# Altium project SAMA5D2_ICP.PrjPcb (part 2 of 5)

## Sheet 04 - SAMA5D2 - DDR.SchDoc
size B; CompanyName: Microchip Technology Inc.; Organization: Microchip Technology; Address1: 2355 West Chandler Blvd.; Address2: Chandler, AZ  85224; Address4: USA; DocumentNumber: 5; SheetNumber: 5; SheetTotal: 15; SheetTitle: SAMA5D2 - DDR3L
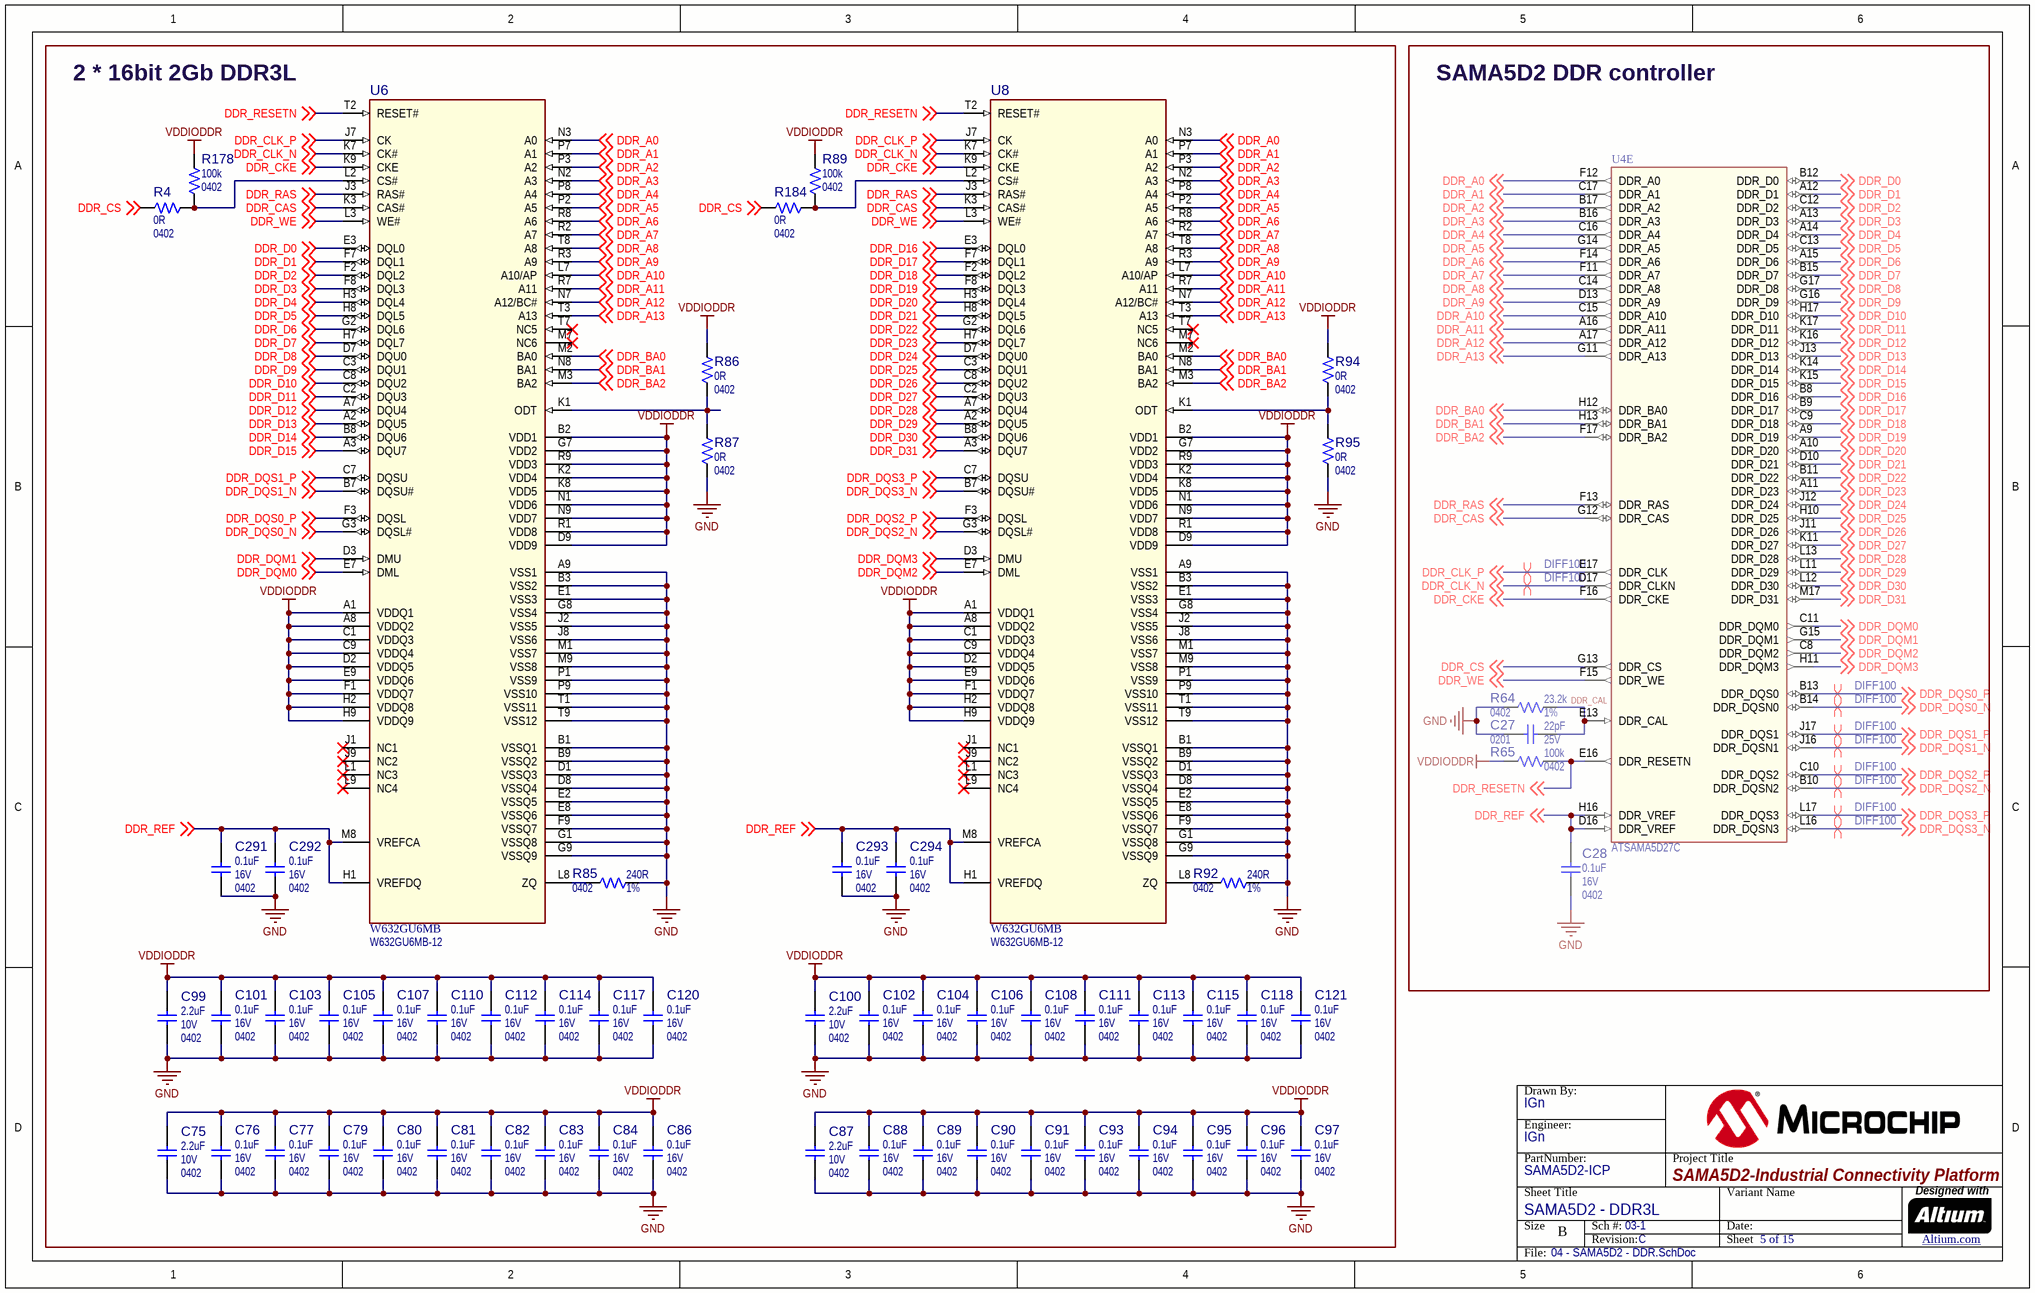
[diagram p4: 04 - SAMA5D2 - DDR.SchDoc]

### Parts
(Parts that share a designator on the sheet are numbered #1, #2 ... from top to bottom, then left to right.)
?#5  (no value)  (graphical)
C27  value 22pF  Voltage: 25V  Package: 0201  [CAP_C_0201]  (hidden comment: Capacitor NP)
C28  value 0.1uF  Voltage: 16V  Package: 0402  [CAP_C_0402]  (hidden comment: Capacitor NP)
C75  value 2.2uF  Voltage: 10V  Package: 0402  [CAP_C_0402]  (hidden comment: Capacitor NP)
C76  value 0.1uF  Voltage: 16V  Package: 0402  [CAP_C_0402]  (hidden comment: Capacitor NP)
C77  value 0.1uF  Voltage: 16V  Package: 0402  [CAP_C_0402]  (hidden comment: Capacitor NP)
C79  value 0.1uF  Voltage: 16V  Package: 0402  [CAP_C_0402]  (hidden comment: Capacitor NP)
C80  value 0.1uF  Voltage: 16V  Package: 0402  [CAP_C_0402]  (hidden comment: Capacitor NP)
C81  value 0.1uF  Voltage: 16V  Package: 0402  [CAP_C_0402]  (hidden comment: Capacitor NP)
C82  value 0.1uF  Voltage: 16V  Package: 0402  [CAP_C_0402]  (hidden comment: Capacitor NP)
C83  value 0.1uF  Voltage: 16V  Package: 0402  [CAP_C_0402]  (hidden comment: Capacitor NP)
C84  value 0.1uF  Voltage: 16V  Package: 0402  [CAP_C_0402]  (hidden comment: Capacitor NP)
C86  value 0.1uF  Voltage: 16V  Package: 0402  [CAP_C_0402]  (hidden comment: Capacitor NP)
C87  value 2.2uF  Voltage: 10V  Package: 0402  [CAP_C_0402]  (hidden comment: Capacitor NP)
C88  value 0.1uF  Voltage: 16V  Package: 0402  [CAP_C_0402]  (hidden comment: Capacitor NP)
C89  value 0.1uF  Voltage: 16V  Package: 0402  [CAP_C_0402]  (hidden comment: Capacitor NP)
C90  value 0.1uF  Voltage: 16V  Package: 0402  [CAP_C_0402]  (hidden comment: Capacitor NP)
C91  value 0.1uF  Voltage: 16V  Package: 0402  [CAP_C_0402]  (hidden comment: Capacitor NP)
C93  value 0.1uF  Voltage: 16V  Package: 0402  [CAP_C_0402]  (hidden comment: Capacitor NP)
C94  value 0.1uF  Voltage: 16V  Package: 0402  [CAP_C_0402]  (hidden comment: Capacitor NP)
C95  value 0.1uF  Voltage: 16V  Package: 0402  [CAP_C_0402]  (hidden comment: Capacitor NP)
C96  value 0.1uF  Voltage: 16V  Package: 0402  [CAP_C_0402]  (hidden comment: Capacitor NP)
C97  value 0.1uF  Voltage: 16V  Package: 0402  [CAP_C_0402]  (hidden comment: Capacitor NP)
C99  value 2.2uF  Voltage: 10V  Package: 0402  [CAP_C_0402]  (hidden comment: Capacitor NP)
C100  value 2.2uF  Voltage: 10V  Package: 0402  [CAP_C_0402]  (hidden comment: Capacitor NP)
C101  value 0.1uF  Voltage: 16V  Package: 0402  [CAP_C_0402]  (hidden comment: Capacitor NP)
C102  value 0.1uF  Voltage: 16V  Package: 0402  [CAP_C_0402]  (hidden comment: Capacitor NP)
C103  value 0.1uF  Voltage: 16V  Package: 0402  [CAP_C_0402]  (hidden comment: Capacitor NP)
C104  value 0.1uF  Voltage: 16V  Package: 0402  [CAP_C_0402]  (hidden comment: Capacitor NP)
C105  value 0.1uF  Voltage: 16V  Package: 0402  [CAP_C_0402]  (hidden comment: Capacitor NP)
C106  value 0.1uF  Voltage: 16V  Package: 0402  [CAP_C_0402]  (hidden comment: Capacitor NP)
C107  value 0.1uF  Voltage: 16V  Package: 0402  [CAP_C_0402]  (hidden comment: Capacitor NP)
C108  value 0.1uF  Voltage: 16V  Package: 0402  [CAP_C_0402]  (hidden comment: Capacitor NP)
C110  value 0.1uF  Voltage: 16V  Package: 0402  [CAP_C_0402]  (hidden comment: Capacitor NP)
C111  value 0.1uF  Voltage: 16V  Package: 0402  [CAP_C_0402]  (hidden comment: Capacitor NP)
C112  value 0.1uF  Voltage: 16V  Package: 0402  [CAP_C_0402]  (hidden comment: Capacitor NP)
C113  value 0.1uF  Voltage: 16V  Package: 0402  [CAP_C_0402]  (hidden comment: Capacitor NP)
C114  value 0.1uF  Voltage: 16V  Package: 0402  [CAP_C_0402]  (hidden comment: Capacitor NP)
C115  value 0.1uF  Voltage: 16V  Package: 0402  [CAP_C_0402]  (hidden comment: Capacitor NP)
C117  value 0.1uF  Voltage: 16V  Package: 0402  [CAP_C_0402]  (hidden comment: Capacitor NP)
C118  value 0.1uF  Voltage: 16V  Package: 0402  [CAP_C_0402]  (hidden comment: Capacitor NP)
C120  value 0.1uF  Voltage: 16V  Package: 0402  [CAP_C_0402]  (hidden comment: Capacitor NP)
C121  value 0.1uF  Voltage: 16V  Package: 0402  [CAP_C_0402]  (hidden comment: Capacitor NP)
C291  value 0.1uF  Voltage: 16V  Package: 0402  [CAP_C_0402]  (hidden comment: Capacitor NP)
C292  value 0.1uF  Voltage: 16V  Package: 0402  [CAP_C_0402]  (hidden comment: Capacitor NP)
C293  value 0.1uF  Voltage: 16V  Package: 0402  [CAP_C_0402]  (hidden comment: Capacitor NP)
C294  value 0.1uF  Voltage: 16V  Package: 0402  [CAP_C_0402]  (hidden comment: Capacitor NP)
R4  value 0R  Package: 0402  [RES_C_0402]  (hidden comment: Resistor)
R64  value 23.2k  Package: 0402  Tolerance: 1%  [RES_C_0402]  (hidden comment: Resistor)
R65  value 100k  Package: 0402  [RES_C_0402]  (hidden comment: Resistor)
R85  value 240R  Package: 0402  Tolerance: 1%  [RES_C_0402]  (hidden comment: Resistor)
R86  value 0R  Package: 0402  [RES_C_0402]  (hidden comment: Resistor)
R87  value 0R  Package: 0402  [RES_C_0402]  (hidden comment: Resistor)
R89  value 100k  Package: 0402  [RES_C_0402]  (hidden comment: Resistor)
R92  value 240R  Package: 0402  Tolerance: 1%  [RES_C_0402]  (hidden comment: Resistor)
R94  value 0R  Package: 0402  [RES_C_0402]  (hidden comment: Resistor)
R95  value 0R  Package: 0402  [RES_C_0402]  (hidden comment: Resistor)
R178  value 100k  Package: 0402  [RES_C_0402]  (hidden comment: Resistor)
R184  value 0R  Package: 0402  [RES_C_0402]  (hidden comment: Resistor)
U4  value ATSAMA5D27C  [LFBGA-289_P0.8_14x14x1.4]  (hidden comment: ATSAMA5D27C LFBGA-289)  (part E of 7)
U6  W632GU6MB  value W632GU6MB-12  [TFBGA-96_13x7.5]
U8  W632GU6MB  value W632GU6MB-12  [TFBGA-96_13x7.5]

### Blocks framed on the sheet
2 * 16bit 2Gb DDR3L: C75-C77 C79-C84 C86-C91 C93-C97 C99-C108 C110-C115 C117 C118 C120 C121 C291-C294 R4 R85-R87 R89 R92 R94 R95 R178 R184 U6 U8
SAMA5D2 DDR controller: C27 C28 R64 R65 U4

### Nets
GND: C27.1 C28.1 C75.1 C76.1 C77.1 C79.1 C80.1 C81.1 C82.1 C83.1 C84.1 C86.1 C87.1 C88.1 C89.1 C90.1 C91.1 C93.1 C94.1 C95.1 C96.1 C97.1 C99.1 C100.1 C101.1 C102.1 C103.1 C104.1 C105.1 C106.1 C107.1 C108.1 C110.1 C111.1 C112.1 C113.1 C114.1 C115.1 C117.1 C118.1 C120.1 C121.1 C291.1 C292.1 C293.1 C294.1 R64.1 R85.1 R87.1 R92.1 R95.1 U6.A9(VSS1) U6.B1(VSSQ1) U6.B3(VSS2) U6.B9(VSSQ2) U6.D1(VSSQ3) U6.D8(VSSQ4) U6.E1(VSS3) U6.E2(VSSQ5) U6.E8(VSSQ6) U6.F9(VSSQ7) U6.G1(VSSQ8) U6.G8(VSS4) U6.G9(VSSQ9) U6.J2(VSS5) U6.J8(VSS6) U6.M1(VSS7) U6.M9(VSS8) U6.P1(VSS9) U6.P9(VSS10) U6.T1(VSS11) U6.T9(VSS12) U8.A9(VSS1) U8.B1(VSSQ1) U8.B3(VSS2) U8.B9(VSSQ2) U8.D1(VSSQ3) U8.D8(VSSQ4) U8.E1(VSS3) U8.E2(VSSQ5) U8.E8(VSSQ6) U8.F9(VSSQ7) U8.G1(VSSQ8) U8.G8(VSS4) U8.G9(VSSQ9) U8.J2(VSS5) U8.J8(VSS6) U8.M1(VSS7) U8.M9(VSS8) U8.P1(VSS9) U8.P9(VSS10) U8.T1(VSS11) U8.T9(VSS12)
VDDIODDR: C75.2 C76.2 C77.2 C79.2 C80.2 C81.2 C82.2 C83.2 C84.2 C86.2 C87.2 C88.2 C89.2 C90.2 C91.2 C93.2 C94.2 C95.2 C96.2 C97.2 C99.2 C100.2 C101.2 C102.2 C103.2 C104.2 C105.2 C106.2 C107.2 C108.2 C110.2 C111.2 C112.2 C113.2 C114.2 C115.2 C117.2 C118.2 C120.2 C121.2 R65.1 R86.1 R89.1 R94.1 R178.1 U6.A1(VDDQ1) U6.A8(VDDQ2) U6.B2(VDD1) U6.C1(VDDQ3) U6.C9(VDDQ4) U6.D2(VDDQ5) U6.D9(VDD9) U6.E9(VDDQ6) U6.F1(VDDQ7) U6.G7(VDD2) U6.H2(VDDQ8) U6.H9(VDDQ9) U6.K2(VDD4) U6.K8(VDD5) U6.N1(VDD6) U6.N9(VDD7) U6.R1(VDD8) U6.R9(VDD3) U8.A1(VDDQ1) U8.A8(VDDQ2) U8.B2(VDD1) U8.C1(VDDQ3) U8.C9(VDDQ4) U8.D2(VDDQ5) U8.D9(VDD9) U8.E9(VDDQ6) U8.F1(VDDQ7) U8.G7(VDD2) U8.H2(VDDQ8) U8.H9(VDDQ9) U8.K2(VDD4) U8.K8(VDD5) U8.N1(VDD6) U8.N9(VDD7) U8.R1(VDD8) U8.R9(VDD3)
DDR_A0: U4.F12(DDR_A0) U6.N3(A0) U8.N3(A0) ; off-sheet DDR_A0
DDR_A1: U4.C17(DDR_A1) U6.P7(A1) U8.P7(A1) ; off-sheet DDR_A1
DDR_A2: U4.B17(DDR_A2) U6.P3(A2) U8.P3(A2) ; off-sheet DDR_A2
DDR_A3: U4.B16(DDR_A3) U6.N2(A3) U8.N2(A3) ; off-sheet DDR_A3
DDR_A4: U4.C16(DDR_A4) U6.P8(A4) U8.P8(A4) ; off-sheet DDR_A4
DDR_A5: U4.G14(DDR_A5) U6.P2(A5) U8.P2(A5) ; off-sheet DDR_A5
DDR_A6: U4.F14(DDR_A6) U6.R8(A6) U8.R8(A6) ; off-sheet DDR_A6
DDR_A7: U4.F11(DDR_A7) U6.R2(A7) U8.R2(A7) ; off-sheet DDR_A7
DDR_A8: U4.C14(DDR_A8) U6.T8(A8) U8.T8(A8) ; off-sheet DDR_A8
DDR_A9: U4.D13(DDR_A9) U6.R3(A9) U8.R3(A9) ; off-sheet DDR_A9
DDR_A10: U4.C15(DDR_A10) U6.L7(A10/AP) U8.L7(A10/AP) ; off-sheet DDR_A10
DDR_A11: U4.A16(DDR_A11) U6.R7(A11) U8.R7(A11) ; off-sheet DDR_A11
DDR_A12: U4.A17(DDR_A12) U6.N7(A12/BC#) U8.N7(A12/BC#) ; off-sheet DDR_A12
DDR_A13: U4.G11(DDR_A13) U6.T3(A13) U8.T3(A13) ; off-sheet DDR_A13
DDR_BA0: U4.H12(DDR_BA0) U6.M2(BA0) U8.M2(BA0) ; off-sheet DDR_BA0
DDR_BA1: U4.H13(DDR_BA1) U6.N8(BA1) U8.N8(BA1) ; off-sheet DDR_BA1
DDR_BA2: U4.F17(DDR_BA2) U6.M3(BA2) U8.M3(BA2) ; off-sheet DDR_BA2
DDR_CAL: C27.2 R64.2 U4.E13(DDR_CAL)
DDR_CAS: U4.G12(DDR_CAS) U6.K3(CAS#) U8.K3(CAS#) ; off-sheet DDR_CAS
DDR_CKE: U4.F16(DDR_CKE) U6.K9(CKE) U8.K9(CKE) ; off-sheet DDR_CKE
DDR_CLK_N: U4.D17(DDR_CLKN) U6.K7(CK#) U8.K7(CK#) ; off-sheet DDR_CLK_N
DDR_CLK_P: U4.E17(DDR_CLK) U6.J7(CK) U8.J7(CK) ; off-sheet DDR_CLK_P
DDR_CS: R4.1 R184.1 U4.G13(DDR_CS) ; off-sheet DDR_CS
DDR_D0: U4.B12(DDR_D0) U6.E3(DQL0) ; off-sheet DDR_D0
DDR_D1: U4.A12(DDR_D1) U6.F7(DQL1) ; off-sheet DDR_D1
DDR_D2: U4.C12(DDR_D2) U6.F2(DQL2) ; off-sheet DDR_D2
DDR_D3: U4.A13(DDR_D3) U6.F8(DQL3) ; off-sheet DDR_D3
DDR_D4: U4.A14(DDR_D4) U6.H3(DQL4) ; off-sheet DDR_D4
DDR_D5: U4.C13(DDR_D5) U6.H8(DQL5) ; off-sheet DDR_D5
DDR_D6: U4.A15(DDR_D6) U6.G2(DQL6) ; off-sheet DDR_D6
DDR_D7: U4.B15(DDR_D7) U6.H7(DQL7) ; off-sheet DDR_D7
DDR_D8: U4.G17(DDR_D8) U6.D7(DQU0) ; off-sheet DDR_D8
DDR_D9: U4.G16(DDR_D9) U6.C3(DQU1) ; off-sheet DDR_D9
DDR_D10: U4.H17(DDR_D10) U6.C8(DQU2) ; off-sheet DDR_D10
DDR_D11: U4.K17(DDR_D11) U6.C2(DQU3) ; off-sheet DDR_D11
DDR_D12: U4.K16(DDR_D12) U6.A7(DQU4) ; off-sheet DDR_D12
DDR_D13: U4.J13(DDR_D13) U6.A2(DQU5) ; off-sheet DDR_D13
DDR_D14: U4.K14(DDR_D14) U6.B8(DQU6) ; off-sheet DDR_D14
DDR_D15: U4.K15(DDR_D15) U6.A3(DQU7) ; off-sheet DDR_D15
DDR_D16: U4.B8(DDR_D16) U8.E3(DQL0) ; off-sheet DDR_D16
DDR_D17: U4.B9(DDR_D17) U8.F7(DQL1) ; off-sheet DDR_D17
DDR_D18: U4.C9(DDR_D18) U8.F2(DQL2) ; off-sheet DDR_D18
DDR_D19: U4.A9(DDR_D19) U8.F8(DQL3) ; off-sheet DDR_D19
DDR_D20: U4.A10(DDR_D20) U8.H3(DQL4) ; off-sheet DDR_D20
DDR_D21: U4.D10(DDR_D21) U8.H8(DQL5) ; off-sheet DDR_D21
DDR_D22: U4.B11(DDR_D22) U8.G2(DQL6) ; off-sheet DDR_D22
DDR_D23: U4.A11(DDR_D23) U8.H7(DQL7) ; off-sheet DDR_D23
DDR_D24: U4.J12(DDR_D24) U8.D7(DQU0) ; off-sheet DDR_D24
DDR_D25: U4.H10(DDR_D25) U8.C3(DQU1) ; off-sheet DDR_D25
DDR_D26: U4.J11(DDR_D26) U8.C8(DQU2) ; off-sheet DDR_D26
DDR_D27: U4.K11(DDR_D27) U8.C2(DQU3) ; off-sheet DDR_D27
DDR_D28: U4.L13(DDR_D28) U8.A7(DQU4) ; off-sheet DDR_D28
DDR_D29: U4.L11(DDR_D29) U8.A2(DQU5) ; off-sheet DDR_D29
DDR_D30: U4.L12(DDR_D30) U8.B8(DQU6) ; off-sheet DDR_D30
DDR_D31: U4.M17(DDR_D31) U8.A3(DQU7) ; off-sheet DDR_D31
DDR_DQM0: U4.C11(DDR_DQM0) U6.E7(DML) ; off-sheet DDR_DQM0
DDR_DQM1: U4.G15(DDR_DQM1) U6.D3(DMU) ; off-sheet DDR_DQM1
DDR_DQM2: U4.C8(DDR_DQM2) U8.E7(DML) ; off-sheet DDR_DQM2
DDR_DQM3: U4.H11(DDR_DQM3) U8.D3(DMU) ; off-sheet DDR_DQM3
DDR_DQS0_N: U4.B14(DDR_DQSN0) U6.G3(DQSL#) ; off-sheet DDR_DQS0_N
DDR_DQS0_P: U4.B13(DDR_DQS0) U6.F3(DQSL) ; off-sheet DDR_DQS0_P
DDR_DQS1_N: U4.J16(DDR_DQSN1) U6.B7(DQSU#) ; off-sheet DDR_DQS1_N
DDR_DQS1_P: U4.J17(DDR_DQS1) U6.C7(DQSU) ; off-sheet DDR_DQS1_P
DDR_DQS2_N: U4.B10(DDR_DQSN2) U8.G3(DQSL#) ; off-sheet DDR_DQS2_N
DDR_DQS2_P: U4.C10(DDR_DQS2) U8.F3(DQSL) ; off-sheet DDR_DQS2_P
DDR_DQS3_N: U4.L16(DDR_DQSN3) U8.B7(DQSU#) ; off-sheet DDR_DQS3_N
DDR_DQS3_P: U4.L17(DDR_DQS3) U8.C7(DQSU) ; off-sheet DDR_DQS3_P
DDR_RAS: U4.F13(DDR_RAS) U6.J3(RAS#) U8.J3(RAS#) ; off-sheet DDR_RAS
DDR_REF: C28.2 C291.2 C292.2 C293.2 C294.2 U4.D16(DDR_VREF) U4.H16(DDR_VREF) U6.H1(VREFDQ) U6.M8(VREFCA) U8.H1(VREFDQ) U8.M8(VREFCA) ; off-sheet DDR_REF
DDR_RESETN: R65.2 U4.E16(DDR_RESETN) U6.T2(RESET#) U8.T2(RESET#) ; off-sheet DDR_RESETN
DDR_WE: U4.F15(DDR_WE) U6.L3(WE#) U8.L3(WE#) ; off-sheet DDR_WE
NetR4_2: R4.2 R178.2 U6.L2(CS#)
NetR85_2: R85.2 U6.L8(ZQ)
NetR86_2: R86.2 R87.2 U6.K1(ODT)
NetR89_2: R89.2 R184.2 U8.L2(CS#)
NetR92_2: R92.2 U8.L8(ZQ)
NetR94_2: R94.2 R95.2 U8.K1(ODT)

Not connected (* = marked no-connect by the designer): U6 J1(NC1)* J9(NC2)* L1(NC3)* L9(NC4)* M7(NC6)* T7(NC5)*; U8 J1(NC1)* J9(NC2)* L1(NC3)* L9(NC4)* M7(NC6)* T7(NC5)*

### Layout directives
differential pair; differential pair class DIFF100; net class DIFF100; rule Matched Net Lengths [Tolerance = 10mil]: DDR_CLK_N, DDR_CLK_P, DDR_DQS0_N, DDR_DQS0_P, DDR_DQS1_N, DDR_DQS1_P, DDR_DQS2_N, DDR_DQS2_P, DDR_DQS3_N, DDR_DQS3_P

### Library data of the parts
?#5 = Title Block B
C27 = CAP1452: Capacitor; Manufacturer 1: TDK Corporation; Manufacturer Part Number 1: C0603C0G1E220K030BA; Description_: CAP CER 22pF 25V 10% NP0 SMD 0201; Dev Tools Status: Design; Tolerance: 10%; Temperature Coeffcient: NP0; Type: Ceramic; Owner: Gabor Bihari; Populated: YES
C28 C76 C77 C79-C84 C86 C88-C91 C93-C97 C101-C108 C110-C115 C117 C118 C120 C121 C291-C294 = CAP1033: Capacitor; Manufacturer 1: Murata; Manufacturer Part Number 1: GRM155R71C104KA88D; Description_: CAP CER 0.1uF 16V 10% X7R SMD 0402; Dev Tools Status: Production; Tolerance: 10%; Temperature Coeffcient: X7R; Type: Ceramic; Owner: Sompoch Loboonlert; Populated: Yes
C75 C87 C99 C100 = CAP1468: Capacitor; Manufacturer 1: TDK Corporation; Manufacturer Part Number 1: C1005X7S1A225K050BC; Description_: CAP CER 2.2uF 10V 10% X7S SMD 0402; Dev Tools Status: Production; Tolerance: 10%; Temperature Coeffcient: X7S; Type: Ceramic; Owner: Sorin Stanoaia; Populated: YES
R4 R86 R94 R184 = RSMT1040: Manufacturer 1: Yageo; Manufacturer Part Number 1: RC0402JR-070RL; Description_: RES TKF 0R 1/16W SMD 0402; Dev Tools Status: Production; Power: 1/16W; Owner: Sompoch Loboonlert; Populated: Yes
R64 = RES1900: Manufacturer 1: Yageo; Manufacturer Part Number 1: RC0402FR-0723K2L; Description_: RES TKF 23.2k 1% 1/16W SMD 0402; Dev Tools Status: Design; Voltage: 50V; Temperature Coeffcient: 100ppm/C; Current: 1A; Power: 1/16W; Owner: Ciprian Abramov; Populated: YES
R65 R89 R178 = RES1011: Manufacturer 1: Panasonic; Manufacturer Part Number 1: ERJ-2RKF1003X; Tolerance: 1%; Description_: RES TKF 100k 1% 1/10W SMD 0402; Dev Tools Status: Production; Voltage: 50V; Temperature Coeffcient: 100ppm/C; Power: 1/10W; Owner: Tad Ahlvers; Populated: YES
R85 R92 = RES1897: Manufacturer 1: Yageo; Manufacturer Part Number 1: RC0402FR-07240RL; Description_: RES TKF 240R 1% 1/16W SMD 0402; Dev Tools Status: Design; Voltage: 50V; Temperature Coeffcient: 100ppm/C; Current: 1A; Power: 1/16W; Owner: Ciprian Abramov; Populated: YES
R87 R95 = RSMT1040: Manufacturer 1: Yageo; Manufacturer Part Number 1: RC0402JR-070RL; Description_: RES TKF 0R 1/16W SMD 0402; Dev Tools Status: Production; Power: 1/16W; Owner: Sompoch Loboonlert; Populated: DNP
U4 = MIC7216: Manufacturer 1: Microchip Technology; Manufacturer Part Number 1: ATSAMA5D27C-CU; Description_: MCHP MPU 32-BIT Cortex®-A5 500MHz ATSAMA5D27C-CU LFBGA-289; MAPS Description: BGA GREEN, IND TEMP,MRLC; Dev Tools Status: Design; Owner: Bogdan Popescu; MPC: 92U037AMBC05; LeadContent: Pb-FREE; TempRange: -40C to +85C; Stage: REL; PackageWidth: 14x14x1.4mm; PackingMedia: TRAY; ForceMinOrderQtyMult: False; MinOrderQty: 1; LeadCount: 289; Program Memory KBytes: 0; Ram: 131072; IOPins: 128; MaxSpeed: 500; OscillatorMHz: 32kHz, 12MHz; ADC Channels: 12; USART: 10; SPI: 7; CAN: 2; USBChannels: 3; Input Capture: 6; mtrlcntrlpwmchannels: 8; CapTouchCH: 16; DigitalTimerQty_16bit: 4; Populated: YES
U6 U8 = IC1526: Manufacturer 1: Winbond Electronics; MCHP-ID: IC1526; Description_: IC DDR3 SDRAM W632GU6MB-12 2GBIT 96TFBGA; Dev Tools Status: Design; Vin: 1.283V to 1.45V; Owner: Dragos Danaila; Populated: YES

## Sheet 05 - SAMA5D2 - PIOs.SchDoc
size B; CompanyName: Microchip Technology Inc.; Organization: Microchip Technology; Address1: 2355 West Chandler Blvd.; Address2: Chandler, AZ  85224; Address4: USA; DocumentNumber: 6; SheetNumber: 6; SheetTotal: 14; SheetTitle: SAMA5D2 - PIOs
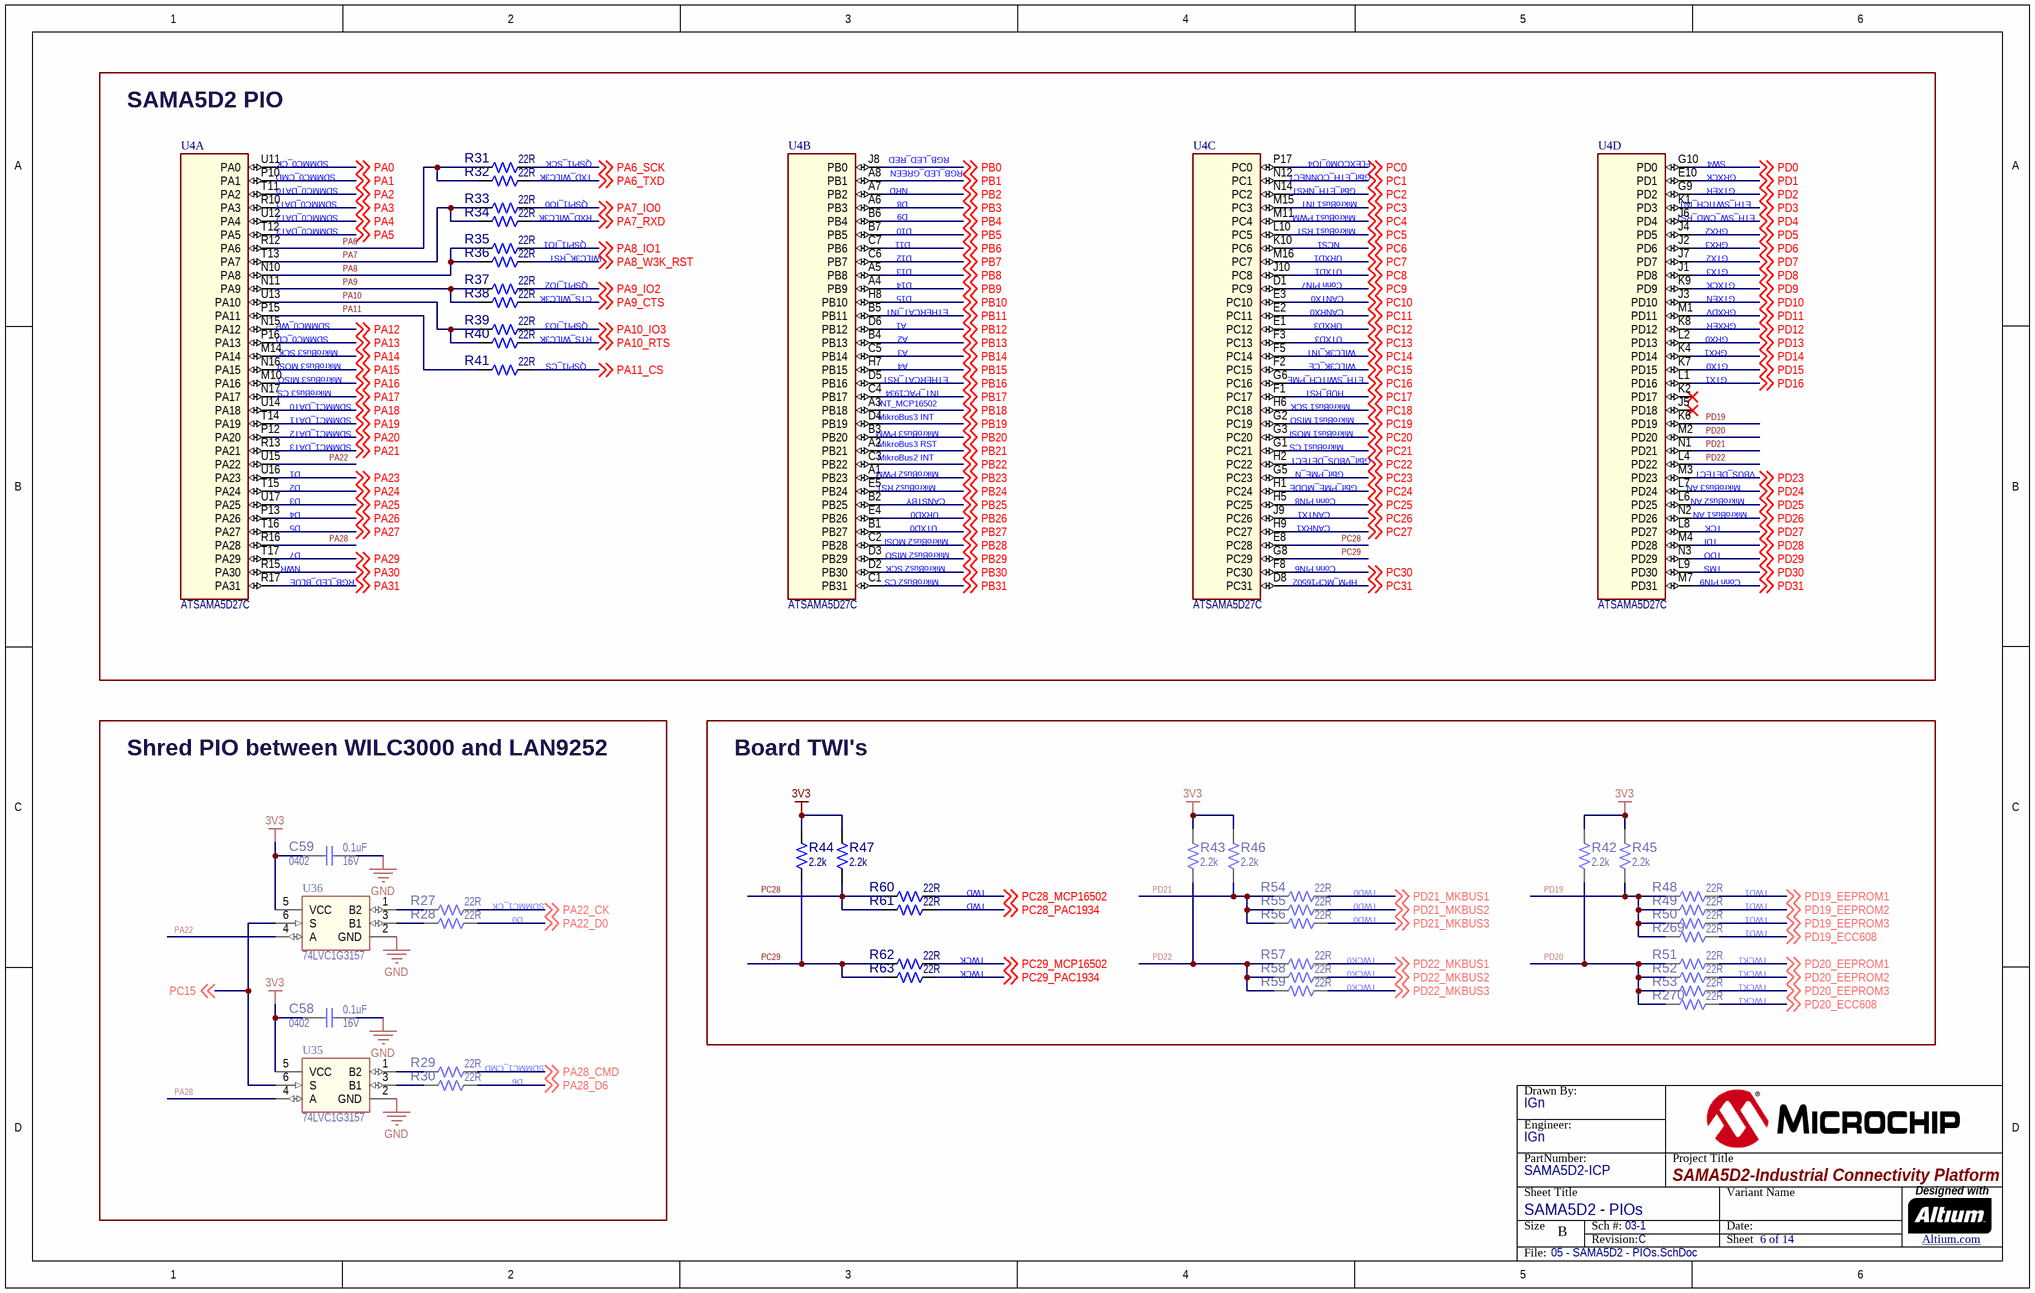
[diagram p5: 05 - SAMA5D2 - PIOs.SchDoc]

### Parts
(Parts that share a designator on the sheet are numbered #1, #2 ... from top to bottom, then left to right.)
?#6  (no value)  (graphical)
C58  value 0.1uF  Voltage: 16V  Package: 0402  [CAP_C_0402]  (hidden comment: Capacitor NP)
C59  value 0.1uF  Voltage: 16V  Package: 0402  [CAP_C_0402]  (hidden comment: Capacitor NP)
R27  value 22R  [RES_C_0402]  (hidden comment: Resistor)
R28  value 22R  [RES_C_0402]  (hidden comment: Resistor)
R29  value 22R  [RES_C_0402]  (hidden comment: Resistor)
R30  value 22R  [RES_C_0402]  (hidden comment: Resistor)
R31  value 22R  [RES_C_0402]  (hidden comment: Resistor)
R32  value 22R  [RES_C_0402]  (hidden comment: Resistor)
R33  value 22R  [RES_C_0402]  (hidden comment: Resistor)
R34  value 22R  [RES_C_0402]  (hidden comment: Resistor)
R35  value 22R  [RES_C_0402]  (hidden comment: Resistor)
R36  value 22R  [RES_C_0402]  (hidden comment: Resistor)
R37  value 22R  [RES_C_0402]  (hidden comment: Resistor)
R38  value 22R  [RES_C_0402]  (hidden comment: Resistor)
R39  value 22R  [RES_C_0402]  (hidden comment: Resistor)
R40  value 22R  [RES_C_0402]  (hidden comment: Resistor)
R41  value 22R  [RES_C_0402]  (hidden comment: Resistor)
R42  value 2.2k  [RES_C_0603]  (hidden comment: Resistor)
R43  value 2.2k  [RES_C_0603]  (hidden comment: Resistor)
R44  value 2.2k  [RES_C_0603]  (hidden comment: Resistor)
R45  value 2.2k  [RES_C_0603]  (hidden comment: Resistor)
R46  value 2.2k  [RES_C_0603]  (hidden comment: Resistor)
R47  value 2.2k  [RES_C_0603]  (hidden comment: Resistor)
R48  value 22R  [RES_C_0402]  (hidden comment: Resistor)
R49  value 22R  [RES_C_0402]  (hidden comment: Resistor)
R50  value 22R  [RES_C_0402]  (hidden comment: Resistor)
R51  value 22R  [RES_C_0402]  (hidden comment: Resistor)
R52  value 22R  [RES_C_0402]  (hidden comment: Resistor)
R53  value 22R  [RES_C_0402]  (hidden comment: Resistor)
R54  value 22R  [RES_C_0402]  (hidden comment: Resistor)
R55  value 22R  [RES_C_0402]  (hidden comment: Resistor)
R56  value 22R  [RES_C_0402]  (hidden comment: Resistor)
R57  value 22R  [RES_C_0402]  (hidden comment: Resistor)
R58  value 22R  [RES_C_0402]  (hidden comment: Resistor)
R59  value 22R  [RES_C_0402]  (hidden comment: Resistor)
R60  value 22R  [RES_C_0402]  (hidden comment: Resistor)
R61  value 22R  [RES_C_0402]  (hidden comment: Resistor)
R62  value 22R  [RES_C_0402]  (hidden comment: Resistor)
R63  value 22R  [RES_C_0402]  (hidden comment: Resistor)
R269  value 22R  [RES_C_0402]  (hidden comment: Resistor)
R270  value 22R  [RES_C_0402]  (hidden comment: Resistor)
U4  value ATSAMA5D27C  [LFBGA-289_P0.8_14x14x1.4]  (hidden comment: ATSAMA5D27C LFBGA-289)  (parts A,B,C,D of 7)
U35  value 74LVC1G3157  [SC-70-6]  (hidden comment: 74LVC1G3157 SOT-23-6_SC-70-6)
U36  value 74LVC1G3157  [SC-70-6]  (hidden comment: 74LVC1G3157 SOT-23-6_SC-70-6)

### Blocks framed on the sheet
SAMA5D2 PIO: R31-R41 U4
Shred PIO between WILC3000 and LAN9252: C58 C59 R27-R30 U35 U36
Board TWI's: R42-R63 R269 R270

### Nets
3V3: C58.2 C59.2 R42.2 R43.2 R44.2 R45.2 R46.2 R47.2 U35.5(VCC) U36.5(VCC)
GND: C58.1 C59.1 U35.2(GND) U36.2(GND)
PA0: U4.U11(PA0) ; off-sheet PA0
PA1: U4.P10(PA1) ; off-sheet PA1
PA2: U4.T11(PA2) ; off-sheet PA2
PA3: U4.R10(PA3) ; off-sheet PA3
PA4: U4.U12(PA4) ; off-sheet PA4
PA5: U4.T12(PA5) ; off-sheet PA5
PA6: R31.1 R32.1 U4.R12(PA6)
PA6_SCK: R31.2 ; off-sheet PA6_SCK
PA6_TXD: R32.2 ; off-sheet PA6_TXD
PA7: R33.1 R34.1 U4.T13(PA7)
PA7_IO0: R33.2 ; off-sheet PA7_IO0
PA7_RXD: R34.2 ; off-sheet PA7_RXD
PA8: R35.1 R36.1 U4.N10(PA8)
PA8_IO1: R35.2 ; off-sheet PA8_IO1
PA8_W3K_RST: R36.2 ; off-sheet PA8_W3K_RST
PA9: R37.1 R38.1 U4.N11(PA9)
PA9_CTS: R38.2 ; off-sheet PA9_CTS
PA9_IO2: R37.2 ; off-sheet PA9_IO2
PA10: R39.1 R40.1 U4.U13(PA10)
PA10_IO3: R39.2 ; off-sheet PA10_IO3
PA10_RTS: R40.2 ; off-sheet PA10_RTS
PA11: R41.1 U4.P15(PA11)
PA11_CS: R41.2 ; off-sheet PA11_CS
PA12: U4.N15(PA12) ; off-sheet PA12
PA13: U4.P16(PA13) ; off-sheet PA13
PA14: U4.M14(PA14) ; off-sheet PA14
PA15: U4.N16(PA15) ; off-sheet PA15
PA16: U4.M10(PA16) ; off-sheet PA16
PA17: U4.N17(PA17) ; off-sheet PA17
PA18: U4.U14(PA18) ; off-sheet PA18
PA19: U4.T14(PA19) ; off-sheet PA19
PA20: U4.P12(PA20) ; off-sheet PA20
PA21: U4.R13(PA21) ; off-sheet PA21
PA22: U4.U15(PA22) U36.4(A)
PA22_CK: R27.2 ; off-sheet PA22_CK
PA22_D0: R28.2 ; off-sheet PA22_D0
PA23: U4.U16(PA23) ; off-sheet PA23
PA24: U4.T15(PA24) ; off-sheet PA24
PA25: U4.U17(PA25) ; off-sheet PA25
PA26: U4.P13(PA26) ; off-sheet PA26
PA27: U4.T16(PA27) ; off-sheet PA27
PA28: U4.R16(PA28) U35.4(A)
PA28_CMD: R29.2 ; off-sheet PA28_CMD
PA28_D6: R30.2 ; off-sheet PA28_D6
PA29: U4.T17(PA29) ; off-sheet PA29
PA30: U4.R15(PA30) ; off-sheet PA30
PA31: U4.R17(PA31) ; off-sheet PA31
PB0: U4.J8(PB0) ; off-sheet PB0
PB1: U4.A8(PB1) ; off-sheet PB1
PB2: U4.A7(PB2) ; off-sheet PB2
PB3: U4.A6(PB3) ; off-sheet PB3
PB4: U4.B6(PB4) ; off-sheet PB4
PB5: U4.B7(PB5) ; off-sheet PB5
PB6: U4.C7(PB6) ; off-sheet PB6
PB7: U4.C6(PB7) ; off-sheet PB7
PB8: U4.A5(PB8) ; off-sheet PB8
PB9: U4.A4(PB9) ; off-sheet PB9
PB10: U4.H8(PB10) ; off-sheet PB10
PB11: U4.B5(PB11) ; off-sheet PB11
PB12: U4.D6(PB12) ; off-sheet PB12
PB13: U4.B4(PB13) ; off-sheet PB13
PB14: U4.C5(PB14) ; off-sheet PB14
PB15: U4.H7(PB15) ; off-sheet PB15
PB16: U4.D5(PB16) ; off-sheet PB16
PB17: U4.C4(PB17) ; off-sheet PB17
PB18: U4.A3(PB18) ; off-sheet PB18
PB19: U4.D4(PB19) ; off-sheet PB19
PB20: U4.B3(PB20) ; off-sheet PB20
PB21: U4.A2(PB21) ; off-sheet PB21
PB22: U4.C3(PB22) ; off-sheet PB22
PB23: U4.A1(PB23) ; off-sheet PB23
PB24: U4.E5(PB24) ; off-sheet PB24
PB25: U4.B2(PB25) ; off-sheet PB25
PB26: U4.E4(PB26) ; off-sheet PB26
PB27: U4.B1(PB27) ; off-sheet PB27
PB28: U4.C2(PB28) ; off-sheet PB28
PB29: U4.D3(PB29) ; off-sheet PB29
PB30: U4.D2(PB30) ; off-sheet PB30
PB31: U4.C1(PB31) ; off-sheet PB31
PC0: U4.P17(PC0) ; off-sheet PC0
PC1: U4.N12(PC1) ; off-sheet PC1
PC2: U4.N14(PC2) ; off-sheet PC2
PC3: U4.M15(PC3) ; off-sheet PC3
PC4: U4.M11(PC4) ; off-sheet PC4
PC5: U4.L10(PC5) ; off-sheet PC5
PC6: U4.K10(PC6) ; off-sheet PC6
PC7: U4.M16(PC7) ; off-sheet PC7
PC8: U4.J10(PC8) ; off-sheet PC8
PC9: U4.D1(PC9) ; off-sheet PC9
PC10: U4.E3(PC10) ; off-sheet PC10
PC11: U4.E2(PC11) ; off-sheet PC11
PC12: U4.E1(PC12) ; off-sheet PC12
PC13: U4.F3(PC13) ; off-sheet PC13
PC14: U4.F5(PC14) ; off-sheet PC14
PC15: U4.F2(PC15) U35.6(S) U36.6(S) ; off-sheet PC15
PC16: U4.G6(PC16) ; off-sheet PC16
PC17: U4.F1(PC17) ; off-sheet PC17
PC18: U4.H6(PC18) ; off-sheet PC18
PC19: U4.G2(PC19) ; off-sheet PC19
PC20: U4.G3(PC20) ; off-sheet PC20
PC21: U4.G1(PC21) ; off-sheet PC21
PC22: U4.H2(PC22) ; off-sheet PC22
PC23: U4.G5(PC23) ; off-sheet PC23
PC24: U4.H1(PC24) ; off-sheet PC24
PC25: U4.H5(PC25) ; off-sheet PC25
PC26: U4.J9(PC26) ; off-sheet PC26
PC27: U4.H9(PC27) ; off-sheet PC27
PC28: R47.1 R60.1 R61.1 U4.E8(PC28)
PC28_MCP16502: R60.2 ; off-sheet PC28_MCP16502
PC28_PAC1934: R61.2 ; off-sheet PC28_PAC1934
PC29: R44.1 R62.1 R63.1 U4.G8(PC29)
PC29_MCP16502: R62.2 ; off-sheet PC29_MCP16502
PC29_PAC1934: R63.2 ; off-sheet PC29_PAC1934
PC30: U4.F8(PC30) ; off-sheet PC30
PC31: U4.D8(PC31) ; off-sheet PC31
PD0: U4.G10(PD0) ; off-sheet PD0
PD1: U4.E10(PD1) ; off-sheet PD1
PD2: U4.G9(PD2) ; off-sheet PD2
PD3: U4.K1(PD3) ; off-sheet PD3
PD4: U4.J6(PD4) ; off-sheet PD4
PD5: U4.J4(PD5) ; off-sheet PD5
PD6: U4.J2(PD6) ; off-sheet PD6
PD7: U4.J7(PD7) ; off-sheet PD7
PD8: U4.J1(PD8) ; off-sheet PD8
PD9: U4.K9(PD9) ; off-sheet PD9
PD10: U4.J3(PD10) ; off-sheet PD10
PD11: U4.M1(PD11) ; off-sheet PD11
PD12: U4.K8(PD12) ; off-sheet PD12
PD13: U4.L2(PD13) ; off-sheet PD13
PD14: U4.K4(PD14) ; off-sheet PD14
PD15: U4.K7(PD15) ; off-sheet PD15
PD16: U4.L1(PD16) ; off-sheet PD16
PD19: R45.1 R48.1 R49.1 R50.1 R269.1 U4.K6(PD19)
PD19_ECC608: R269.2 ; off-sheet PD19_ECC608
PD19_EEPROM1: R48.2 ; off-sheet PD19_EEPROM1
PD19_EEPROM2: R49.2 ; off-sheet PD19_EEPROM2
PD19_EEPROM3: R50.2 ; off-sheet PD19_EEPROM3
PD20: R42.1 R51.1 R52.1 R53.1 R270.1 U4.M2(PD20)
PD20_ECC608: R270.2 ; off-sheet PD20_ECC608
PD20_EEPROM1: R51.2 ; off-sheet PD20_EEPROM1
PD20_EEPROM2: R52.2 ; off-sheet PD20_EEPROM2
PD20_EEPROM3: R53.2 ; off-sheet PD20_EEPROM3
PD21: R46.1 R54.1 R55.1 R56.1 U4.N1(PD21)
PD21_MKBUS1: R54.2 ; off-sheet PD21_MKBUS1
PD21_MKBUS2: R55.2 ; off-sheet PD21_MKBUS2
PD21_MKBUS3: R56.2 ; off-sheet PD21_MKBUS3
PD22: R43.1 R57.1 R58.1 R59.1 U4.L4(PD22)
PD22_MKBUS1: R57.2 ; off-sheet PD22_MKBUS1
PD22_MKBUS2: R58.2 ; off-sheet PD22_MKBUS2
PD22_MKBUS3: R59.2 ; off-sheet PD22_MKBUS3
PD23: U4.M3(PD23) ; off-sheet PD23
PD24: U4.L7(PD24) ; off-sheet PD24
PD25: U4.L6(PD25) ; off-sheet PD25
PD26: U4.N2(PD26) ; off-sheet PD26
PD27: U4.L8(PD27) ; off-sheet PD27
PD28: U4.M4(PD28) ; off-sheet PD28
PD29: U4.N3(PD29) ; off-sheet PD29
PD30: U4.L9(PD30) ; off-sheet PD30
PD31: U4.M7(PD31) ; off-sheet PD31
NetR27_1: R27.1 U36.1(B2)
NetR28_1: R28.1 U36.3(B1)
NetR29_1: R29.1 U35.1(B2)
NetR30_1: R30.1 U35.3(B1)

Not connected (* = marked no-connect by the designer): U4 J5(PD18)* K2(PD17)*

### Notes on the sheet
- (near U4) SDMMC0_CK
- (near U4) SDMMC0_CMD
- QSPI1_SCK
- TXD_WILC3K
- (near U4) RGB_LED_RED
- (near U4) RGB_LED_GREEN
- (near U4) Gbit_ETH_CONNECT
- FLEXCOM0_IO4
- (near U4) SW4
- (near U4) GRXCK
- (near U4) SDMMC0_DAT1
- (near U4) SDMMC0_DAT2
- (near U4) SDMMC0_DAT0
- (near U4) SDMMC0_DAT3
- QSPI1_IO1
- QSPI1_IO0
- RXD_WILC3K
- (near U4) D8
- (near U4) D9
- (near U4) NRD
- (near U4) D11
- (near U4) D10
- NCS1
- (near U4) Gbit_ETH_NRST
- (near U4) MikroBus1 PWM
- (near U4) MikroBus1 RST
- (near U4) MikroBus1 INT
- (near U4) GRX3
- (near U4) GRX2
- (near U4) GTXER
- (near U4) ETH_SWTICH_INT
- (near U4) ETH_SW_CMD_RST
- QSPI1_IO2
- CTS_WILC3K
- WILC3K_RST
- (near U4) D12
- (near U4) D13
- (near U4) D14
- (near U4) D15
- (near U4) ETHERCAT_INT
- URXD1
- UTXD1
- (near U4) Conn PIN7
- CANRX0
- CANTX0
- (near U4) GTX3
- (near U4) GTX2
- (near U4) GTXEN
- (near U4) GTXCK
- (near U4) GRXDV
- (near U4) SDMMC0_CD
- (near U4) SDMMC0_WP
- (near U4) MikroBus3 SCK
- (near U4) MikroBus3 MOSI
- (near U4) MikroBus3 MISO
- QSPI1_CS
- QSPI1_IO3
- RTS_WILC3K
- (near U4) A1
- (near U4) A2
- (near U4) A3
- (near U4) A4
- (near U4) ETHERCAT_RST
- URXD3
- UTXD3
- (near U4) WILC3K_INT
- WILC3K_CE
- (near U4) ETH_SWITCH_PME
- (near U4) GTX1
- (near U4) GRX1
- (near U4) GRX0
- (near U4) GTX0
- (near U4) GRXER
- (near U4) MikroBus3 CS
- SDMMC1_DAT3
- SDMMC1_DAT2
- SDMMC1_DAT1
- SDMMC1_DAT0
- (near U4) MikroBus3 INT
- (near U4) INT_MCP16502
- (near U4) MikroBus3 PWM
- (near U4) INT_PAC1934
- (near U4) HUB_RST
- (near U4) MikroBus1 CS
- (near U4) MikroBus1 SCK
- (near U4) MikroBus1 MOSI
- (near U4) MikroBus1 MISO
- (near U4) D1
- (near U4) D2
- (near U4) D3
- (near U4) D4
- (near U4) MikroBus3 RST
- (near U4) MikroBus2 INT
- (near U4) MikroBus2 RST
- (near U4) MikroBus2 PWM
- URXD0
- CANSTBY
- (near U4) CANTX1
- (near U4) Conn PIN8
- (near U4) Gbit_PME_N
- (near U4) Gbit_PME_MODE
- (near U4) Gbit_VBUS_DETECT
- (near U4) MikroBus3 AN
- (near U4) MikroBus2 AN
- (near U4) MikroBus1 AN
- (near U4) VBUS_DETECT
- (near U4) D5
- (near U4) D7
- (near U4) NWR
- RGB_LED_BLUE
- UTXD0
- (near U4) MikroBus2 CS
- (near U4) MikroBus2 SCK
- (near U4) MikroBus2 MOSI
- (near U4) MikroBus2 MISO
- (near U4) CANRX1
- (near U4) Conn PIN6
- (near U4) HPM_MCP16502
- (near U4) TDI
- (near U4) TMS
- (near U4) TCK
- (near U4) TDO
- (near U4) Conn PIN9
- D0
- SDMMC1_CK
- TWD
- TWD0
- TWD1
- TWCK
- TWCK0
- TWCK1
- D6
- SDMMC1_CMD

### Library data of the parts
?#6 = Title Block B
C58 C59 = CAP1033: as C28 on sheet 04 - SAMA5D2 - DDR
R27-R41 R48-R63 R269 R270 = RES1474: Manufacturer 1: Panasonic Electronic Components; Manufacturer Part Number 1: ERJ-2RKF22R0X; Tolerance: 1%; Description_: RES TKF 22R 1% 1/20W SMD 0402; Dev Tools Status: Production; Temperature Coeffcient: 100ppm/C; Circuit Type: Isolated; Power: 1/10W; Owner: Mike Ragsdale; Populated: YES
R42-R47 = RES1130: Manufacturer 1: Panasonic; Manufacturer Part Number 1: ERJ-3EKF2201V; Tolerance: 1%; Description_: RES TKF 2.2k 1% 1/10W SMD 0603; Dev Tools Status: Production; Voltage: 75V; Temperature Coeffcient: 100ppm/C; Power: 1/10W; Owner: Bogdan P (M91398); Populated: Yes
U4 = MIC7216: as U4 on sheet 04 - SAMA5D2 - DDR
U35 U36 = IC1149: Manufacturer 1: Texas Instruments; Manufacturer Part Number 1: SN74LVC1G3157DCKR; MCHP-ID: IC1149; Description_: IC SWITCH SPDT 74LVC1G3157 SC-70-6; Dev Tools Status: Production; Owner: Stephen Humberd; Populated: YES

## Sheet 06 - USB.SchDoc
size B; CompanyName: Microchip Technology Inc.; Organization: Microchip Technology; Address1: 2355 West Chandler Blvd.; Address2: Chandler, AZ  85224; Address4: USA; DocumentNumber: 7; SheetNumber: 7; SheetTotal: 15; SheetTitle: USBs
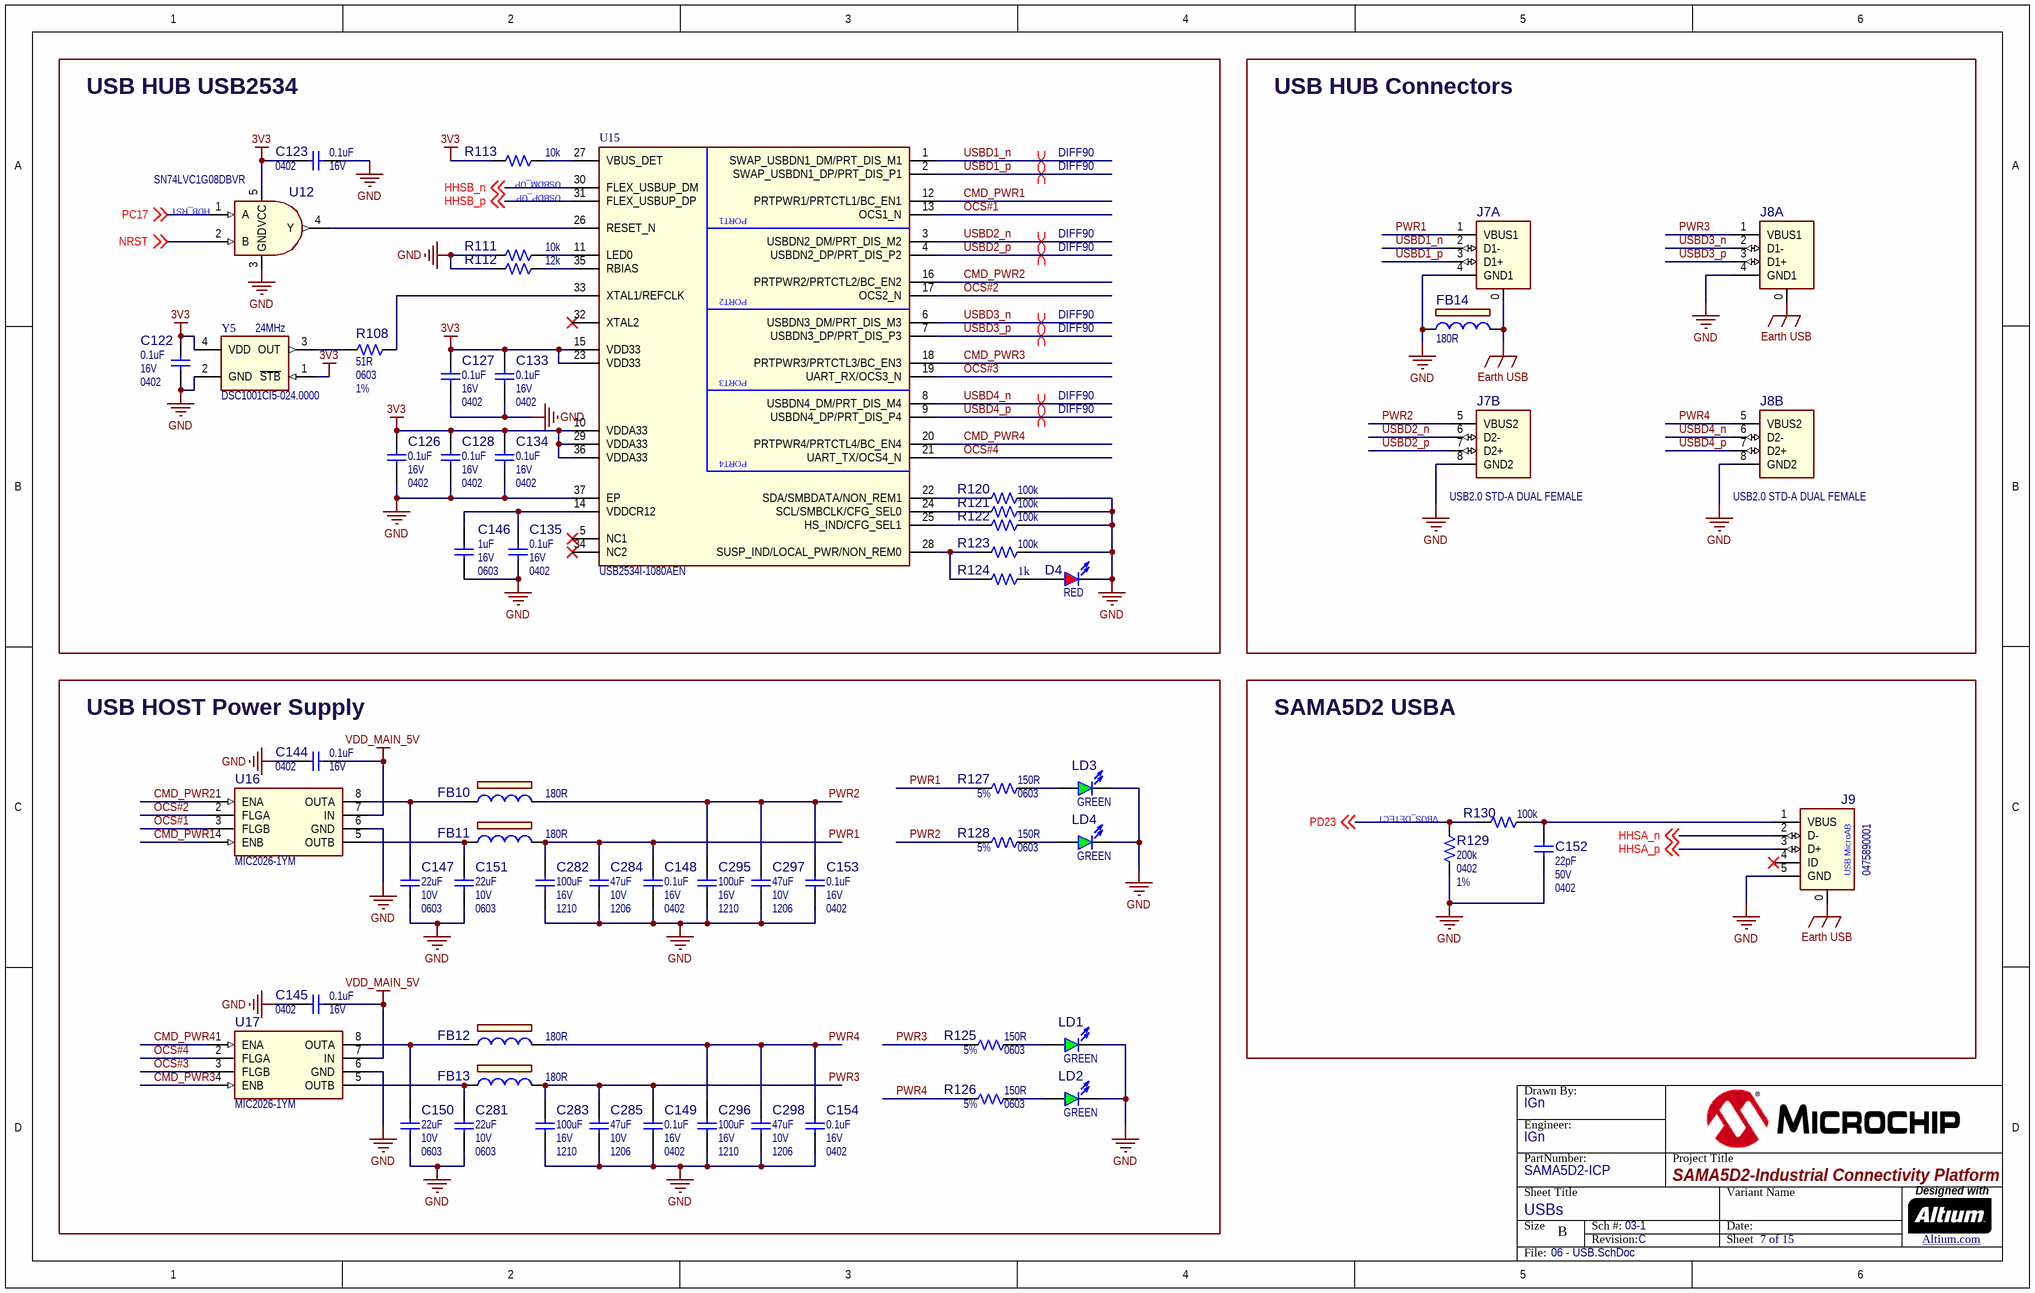
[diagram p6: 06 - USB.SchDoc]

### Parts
(Parts that share a designator on the sheet are numbered #1, #2 ... from top to bottom, then left to right.)
?#7  (no value)  (graphical)
C122  value 0.1uF  Voltage: 16V  Package: 0402  [CAP_C_0402]  (hidden comment: Capacitor NP)
C123  value 0.1uF  Voltage: 16V  Package: 0402  [CAP_C_0402]  (hidden comment: Capacitor NP)
C126  value 0.1uF  Voltage: 16V  Package: 0402  [CAP_C_0402]  (hidden comment: Capacitor NP)
C127  value 0.1uF  Voltage: 16V  Package: 0402  [CAP_C_0402]  (hidden comment: Capacitor NP)
C128  value 0.1uF  Voltage: 16V  Package: 0402  [CAP_C_0402]  (hidden comment: Capacitor NP)
C133  value 0.1uF  Voltage: 16V  Package: 0402  [CAP_C_0402]  (hidden comment: Capacitor NP)
C134  value 0.1uF  Voltage: 16V  Package: 0402  [CAP_C_0402]  (hidden comment: Capacitor NP)
C135  value 0.1uF  Voltage: 16V  Package: 0402  [CAP_C_0402]  (hidden comment: Capacitor NP)
C144  value 0.1uF  Voltage: 16V  Package: 0402  [CAP_C_0402]  (hidden comment: Capacitor NP)
C145  value 0.1uF  Voltage: 16V  Package: 0402  [CAP_C_0402]  (hidden comment: Capacitor NP)
C146  value 1uF  Voltage: 16V  Package: 0603  [CAP_C_0603]  (hidden comment: Capacitor NP)
C147  value 22uF  Voltage: 10V  Package: 0603  [CAP_C_0603]  (hidden comment: Capacitor NP)
C148  value 0.1uF  Voltage: 16V  Package: 0402  [CAP_C_0402]  (hidden comment: Capacitor NP)
C149  value 0.1uF  Voltage: 16V  Package: 0402  [CAP_C_0402]  (hidden comment: Capacitor NP)
C150  value 22uF  Voltage: 10V  Package: 0603  [CAP_C_0603]  (hidden comment: Capacitor NP)
C151  value 22uF  Voltage: 10V  Package: 0603  [CAP_C_0603]  (hidden comment: Capacitor NP)
C152  value 22pF  Voltage: 50V  Package: 0402  [CAP_C_0402]  (hidden comment: Capacitor NP)
C153  value 0.1uF  Voltage: 16V  Package: 0402  [CAP_C_0402]  (hidden comment: Capacitor NP)
C154  value 0.1uF  Voltage: 16V  Package: 0402  [CAP_C_0402]  (hidden comment: Capacitor NP)
C281  value 22uF  Voltage: 10V  Package: 0603  [CAP_C_0603]  (hidden comment: Capacitor NP)
C282  value 100uF  Voltage: 16V  Package: 1210  [CAP_C_1210]  (hidden comment: Capacitor NP)
C283  value 100uF  Voltage: 16V  Package: 1210  [CAP_C_1210]  (hidden comment: Capacitor NP)
C284  value 47uF  Voltage: 10V  Package: 1206  [CAP_C_1206]  (hidden comment: Capacitor NP)
C285  value 47uF  Voltage: 10V  Package: 1206  [CAP_C_1206]  (hidden comment: Capacitor NP)
C295  value 100uF  Voltage: 16V  Package: 1210  [CAP_C_1210]  (hidden comment: Capacitor NP)
C296  value 100uF  Voltage: 16V  Package: 1210  [CAP_C_1210]  (hidden comment: Capacitor NP)
C297  value 47uF  Voltage: 10V  Package: 1206  [CAP_C_1206]  (hidden comment: Capacitor NP)
C298  value 47uF  Voltage: 10V  Package: 1206  [CAP_C_1206]  (hidden comment: Capacitor NP)
D4  value RED  [LED_0402_RED]  (hidden comment: LED_red)
FB10  value 180R  [IND_C_0603]  (hidden comment: Ferrite Bead)
FB11  value 180R  [IND_C_0603]  (hidden comment: Ferrite Bead)
FB12  value 180R  [IND_C_0603]  (hidden comment: Ferrite Bead)
FB13  value 180R  [IND_C_0603]  (hidden comment: Ferrite Bead)
FB14  value 180R  [IND_C_0603]  (hidden comment: Ferrite Bead)
J7  CON USB2.0 A DUAL  [CON_USB2.0-A_Dual_RCPT_TH_RA_AMN_AU-Y1008-2]  (value not drawn)  (parts A,B of 2)
J8  CON USB2.0 A DUAL  [CON_USB2.0-A_Dual_RCPT_TH_RA_AMN_AU-Y1008-2]  (value not drawn)  (parts A,B of 2)
J9  value 0475890001  [CON_USB_Micro-AB_SMD_RA_MOLEX_0475890001]  (hidden comment: CON USB2.0 Mini_Micro)
LD1  value GREEN  [LED_0603_GREEN]  (hidden comment: LED_green)
LD2  value GREEN  [LED_0603_GREEN]  (hidden comment: LED_green)
LD3  value GREEN  [LED_0603_GREEN]  (hidden comment: LED_green)
LD4  value GREEN  [LED_0603_GREEN]  (hidden comment: LED_green)
R108  value 51R  Package: 0603  Tolerance: 1%  [RES_C_0603]  (hidden comment: Resistor)
R111  value 10k  [RES_C_0402]  (hidden comment: Resistor)
R112  value 12k  [RES_C_0402]  (hidden comment: Resistor)
R113  value 10k  [RES_C_0402]  (hidden comment: Resistor)
R120  value 100k  [RES_C_0402]  (hidden comment: Resistor)
R121  value 100k  [RES_C_0402]  (hidden comment: Resistor)
R122  value 100k  [RES_C_0402]  (hidden comment: Resistor)
R123  value 100k  [RES_C_0402]  (hidden comment: Resistor)
R124  value 1k  [RES_C_0603]  (hidden comment: Resistor)
R125  value 150R  Package: 0603  Tolerance: 5%  [RES_C_0603]  (hidden comment: Resistor)
R126  value 150R  Package: 0603  Tolerance: 5%  [RES_C_0603]  (hidden comment: Resistor)
R127  value 150R  Package: 0603  Tolerance: 5%  [RES_C_0603]  (hidden comment: Resistor)
R128  value 150R  Package: 0603  Tolerance: 5%  [RES_C_0603]  (hidden comment: Resistor)
R129  value 200k  Package: 0402  Tolerance: 1%  [RES_C_0402]  (hidden comment: Resistor)
R130  value 100k  [RES_C_0402]  (hidden comment: Resistor)
U12  value SN74LVC1G08DBVR  [SOT-23-5]  (hidden comment: 74XX1G08_9 SOT-23-5)
U15  value USB2534I-1080AEN  [QFN-36_6x6_EP3.7x3.7]  (hidden comment: USB2534 SQFN-36)
U16  value MIC2026-1YM  [SOIC-8]  (hidden comment: MIC2026-2076 DIP-8 SOIC-8)
U17  value MIC2026-1YM  [SOIC-8]  (hidden comment: MIC2026-2076 DIP-8 SOIC-8)
Y5  value 24MHz  Manufacturer Part Number 1: DSC1001CI5-024.0000  [CDFN-4_3.2X2.5]  (hidden comment: DSC10xx DFN-4)

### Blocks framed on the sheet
USB HUB USB2534: C122 C123 C126-C128 C133-C135 C146 D4 R108 R111-R113 R120-R124 U12 U15 Y5
USB HUB Connectors: FB14 J7 J8
USB HOST Power Supply: C144 C145 C147-C151 C153 C154 C281-C285 C295-C298 FB10-FB13 LD1-LD4 R125-R128 U16 U17
SAMA5D2 USBA: C152 J9 R129 R130

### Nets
3V3: C122.2 C123.2 C126.2 C127.2 C128.2 C133.2 C134.2 R113.2 U12.5(VCC) U15.10(VDDA33) U15.15(VDD33) U15.23(VDD33) U15.29(VDDA33) U15.36(VDDA33) Y5.1(~{STB}) Y5.4(VDD)
Earth USB: FB14.2 J7.0(SHLD) J8.0(SHLD) J9.0(SHLD)
GND: C122.1 C123.1 C126.1 C127.1 C128.1 C133.1 C134.1 C135.1 C144.2 C145.2 C146.1 C147.1 C148.1 C149.1 C150.1 C151.1 C152.1 C153.1 C154.1 C281.1 C282.1 C283.1 C284.1 C285.1 C295.1 C296.1 C297.1 C298.1 D4.2(K) FB14.1 J7.4(GND1) J7.8(GND2) J8.4(GND1) J8.8(GND2) J9.5(GND) LD1.2(K) LD2.2(K) LD3.2(K) LD4.2(K) R111.1 R112.2 R120.2 R121.2 R122.2 R123.2 R129.1 U12.3(GND) U15.37(EP) U16.6(GND) U17.6(GND) Y5.2(GND)
VDD_MAIN_5V: C144.1 C145.1 U16.7(IN) U17.7(IN)
CMD_PWR1: U15.12(PRTPWR1/PRTCTL1/BC_EN1) U16.4(ENB)
CMD_PWR2: U15.16(PRTPWR2/PRTCTL2/BC_EN2) U16.1(ENA)
CMD_PWR3: U15.18(PRTPWR3/PRTCTL3/BC_EN3) U17.4(ENB)
CMD_PWR4: U15.20(PRTPWR4/PRTCTL4/BC_EN4) U17.1(ENA)
HHSA_n: J9.2(D-) ; off-sheet HHSA_n
HHSA_p: J9.3(D+) ; off-sheet HHSA_p
HHSB_n: U15.30(FLEX_USBUP_DM) ; off-sheet HHSB_n
HHSB_p: U15.31(FLEX_USBUP_DP) ; off-sheet HHSB_p
NRST: U12.2(B) ; off-sheet NRST
OCS#1: U15.13(OCS1_N) U16.3(FLGB)
OCS#2: U15.17(OCS2_N) U16.2(FLGA)
OCS#3: U15.19(UART_RX/OCS3_N) U17.3(FLGB)
OCS#4: U15.21(UART_TX/OCS4_N) U17.2(FLGA)
PC17: U12.1(A) ; off-sheet PC17
PD23: R129.2 R130.1 ; off-sheet PD23
PWR1: C148.2 C282.2 C284.2 FB11.2 J7.1(VBUS1) R127.1
PWR2: C153.2 C295.2 C297.2 FB10.2 J7.5(VBUS2) R128.1
PWR3: C149.2 C283.2 C285.2 FB13.2 J8.1(VBUS1) R125.1
PWR4: C154.2 C296.2 C298.2 FB12.2 J8.5(VBUS2) R126.1
USBD1_n: J7.2(D1-) U15.1(SWAP_USBDN1_DM/PRT_DIS_M1)
USBD1_p: J7.3(D1+) U15.2(SWAP_USBDN1_DP/PRT_DIS_P1)
USBD2_n: J7.6(D2-) U15.3(USBDN2_DM/PRT_DIS_M2)
USBD2_p: J7.7(D2+) U15.4(USBDN2_DP/PRT_DIS_P2)
USBD3_n: J8.2(D1-) U15.6(USBDN3_DM/PRT_DIS_M3)
USBD3_p: J8.3(D1+) U15.7(USBDN3_DP/PRT_DIS_P3)
USBD4_n: J8.6(D2-) U15.8(USBDN4_DM/PRT_DIS_M4)
USBD4_p: J8.7(D2+) U15.9(USBDN4_DP/PRT_DIS_P4)
NetC135_2: C135.2 C146.2 U15.14(VDDCR12)
NetC147_2: C147.2 FB10.1 U16.8(OUTA)
NetC150_2: C150.2 FB12.1 U17.8(OUTA)
NetC151_2: C151.2 FB11.1 U16.5(OUTB)
NetC152_2: C152.2 J9.1(VBUS) R130.2
NetC281_2: C281.2 FB13.1 U17.5(OUTB)
NetD4_1: D4.1(A) R124.2
NetLD1_1: LD1.1(A) R125.2
NetLD2_1: LD2.1(A) R126.2
NetLD3_1: LD3.1(A) R127.2
NetLD4_1: LD4.1(A) R128.2
NetR108_1: R108.1 Y5.3(OUT)
NetR108_2: R108.2 U15.33(XTAL1/REFCLK)
NetR111_2: R111.2 U15.11(LED0)
NetR112_1: R112.1 U15.35(RBIAS)
NetR113_1: R113.1 U15.27(VBUS_DET)
NetR120_1: R120.1 U15.22(SDA/SMBDATA/NON_REM1)
NetR121_1: R121.1 U15.24(SCL/SMBCLK/CFG_SEL0)
NetR122_1: R122.1 U15.25(HS_IND/CFG_SEL1)
NetR123_1: R123.1 R124.1 U15.28(SUSP_IND/LOCAL_PWR/NON_REM0)
NetU12_4: U12.4(Y) U15.26(RESET_N)

Not connected (* = marked no-connect by the designer): J9 4(ID)*; U15 5(NC1)* 32(XTAL2)* 34(NC2)*

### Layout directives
differential pair; differential pair class DIFF90; net class DIFF90; rule Matched Net Lengths [Tolerance = 10mil]: USBD1_n, USBD1_p, USBD2_n, USBD2_p, USBD3_n, USBD3_p, USBD4_n, USBD4_p

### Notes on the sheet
- (near U12) HUB_RST
- USBDP_UP
- (near R113) USBDM_UP
- (near R129) VBUS_DETECT
- (near J9) USB MicroAB

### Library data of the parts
?#7 = Title Block B
C122 C123 C126-C128 C133-C135 C144 C145 C148 C149 C153 C154 = CAP1033: as C28 on sheet 04 - SAMA5D2 - DDR
C146 = CAP0265: Capacitor; Manufacturer 1: AVX; Manufacturer Part Number 1: 0603YD105KAT2A; Description_: CAP CER 1uF 16V 10% X5R SMD 0603; Dev Tools Status: Production; Tolerance: 10%; Temperature Coeffcient: X5R; Type: Ceramic; Populated: Yes
C147 C150 C151 C281 = CAP1648: Capacitor; Manufacturer 1: TDK Corporation; Manufacturer Part Number 1: C1608X5R1A226M080AC; Description_: CAP CER 22uF 10V 20% X5R SMD 0603; Dev Tools Status: Production; Tolerance: 20%; Temperature Coeffcient: X5R; Type: Ceramic; Owner: Razvan Cristescu; Populated: YES
C152 = CAP1042: Capacitor; Manufacturer 1: Murata; Manufacturer Part Number 1: GRM1555C1H220JZ01D; Description_: CAP CER 22pF 50V 5% NP0 SMD 0402; Dev Tools Status: Production; Tolerance: 5%; Temperature Coeffcient: NP0; Type: Ceramic; Owner: Sompoch Loboonlert; Populated: Yes
C282 C283 C295 C296 = CAP1558: Capacitor; Manufacturer 1: Yageo; Manufacturer Part Number 1: CC1210MKX5R7BB107; Description_: CAP CER 100uF 16V 20% X5R SMD 1210; Dev Tools Status: Production; Tolerance: 20%; Temperature Coeffcient: X5R; Type: Ceramic; Owner: Mike Ragsdale; Populated: YES
C284 C285 C297 C298 = CAP0507: Capacitor; Manufacturer 1: KEMET; Manufacturer Part Number 1: C1206C476M8PACTU; Description_: CAP CER 47uF 10V 20% X5R SMD 1206; Dev Tools Status: Production; Tolerance: 20%; Temperature Coeffcient: X5R; Type: Ceramic; Populated: Yes
D4 = DIODE1426: LED; Manufacturer 1: Rohm Semiconductor; Manufacturer Part Number 1: SML-P11VTT86; Description_: DIO LED RED 1.8V 1mA 4mcd CLEAR SMD 0402; Dev Tools Status: Design; Type: LED Single; Forward Current: 1mA; Power: 50mW; Reverse Current: 10uA; Reverse Voltage: 5V; Owner: Ilie Galan; Populated: YES
FB10-FB14 = IND1453: FERRITE 180R 1.5A SMD 0603; Manufacturer 1: Murata Electronics North America; Manufacturer Part Number 1: BLM18PG181SN1D; Dev Tools Status: Production; Owner: Dragos Danaila; DCR: 0.09R; Test Frequency: 100MHz; Populated: YES
J7 J8 = CON1430: Connector USB DUAL; Manufacturer 1: Assmann WSW Components; Manufacturer Part Number 1: AU-Y1008-2; Value: USB2.0 STD-A DUAL FEMALE; Description_: CON USB2.0 STD-A DUAL FEMALE TH R/A; Dev Tools Status: Design; Owner: Sorin Stanoaia; Current: 1.5A; Populated: YES
J9 = CON1753: Connector USB Mini; Manufacturer 1: Molex, LLC; Description_: CON USB2.0 MICRO-AB FEMALE SMD R/A; Dev Tools Status: Design; Owner: Dragos Danaila; Voltage: 30VAC; Current: 1A, 1.8A; Populated: YES
LD1-LD4 = DIODE1155: LED; Manufacturer 1: Lite-On Inc; Manufacturer Part Number 1: LTST-C191KGKT; Description_: DIO LED GREEN 2V 30mA 35mcd Clear SMD 0603; Dev Tools Status: Production; Type: LED Single; Forward Current: 30mA; Power: 75mW; Reverse Voltage: 5V; Owner: Tad Ahlvers; Populated: YES
R108 = RES1384: Manufacturer 1: Yageo; Manufacturer Part Number 1: RC0603FR-0751RL; Description_: RES TKF 51R 1% 1/10W SMD 0603; Dev Tools Status: Production; Voltage: 50V; Temperature Coeffcient: 100ppm/C; Circuit Type: Isolated; Power: 1/10W; Owner: Jairuz Agang-ang; Populated: YES
R111 = RSMT1019: Manufacturer 1: Panasonic; Manufacturer Part Number 1: ERJ-2RKF1002X; Tolerance: 1%; Description_: RES TKF 10k 1% 1/10W SMD 0402; Dev Tools Status: Production; Voltage: 50V; Temperature Coeffcient: 100ppm/C; Power: 1/10W; Owner: Brent Lanphear; Populated: DNP
R112 = RES1021: Manufacturer 1: Rohm Semiconductor; Manufacturer Part Number 1: MCR01MZPF1202; Tolerance: 1%; Description_: RES TKF 12k 1% 1/16W SMD 0402; Dev Tools Status: Production; Voltage: 50V; Temperature Coeffcient: 400ppm/C; Power: 1/16W; Owner: Tad Ahlvers; Populated: YES
R113 = RSMT1019: Manufacturer 1: Panasonic; Manufacturer Part Number 1: ERJ-2RKF1002X; Tolerance: 1%; Description_: RES TKF 10k 1% 1/10W SMD 0402; Dev Tools Status: Production; Voltage: 50V; Temperature Coeffcient: 100ppm/C; Power: 1/10W; Owner: Brent Lanphear; Populated: Yes
R120-R123 R130 = RES1011: as R65 on sheet 04 - SAMA5D2 - DDR
R124 = RSMT0138: Manufacturer 1: Panasonic; Manufacturer Part Number 1: ERJ-3EKF1001V; Tolerance: 1%; Description_: RES TKF 1k 1% 1/10W SMD 0603; Dev Tools Status: Production; Voltage: 75V; Temperature Coeffcient: 100ppm/C; Power: 1/10W; Populated: Yes
R125-R128 = RSMT0206: Manufacturer 1: Panasonic; Manufacturer Part Number 1: ERJ-3GEYJ151V; Description_: RES TKF 150R 5% 1/10W SMD 0603; Dev Tools Status: Production; Voltage: 75V; Temperature Coeffcient: 200ppm/C; Power: 1/10W; Populated: Yes
R129 = RES1424: Manufacturer 1: Panasonic; Manufacturer Part Number 1: ERJ-2RKF2003X; Description_: RES TKF 200k 1% 1/10W SMD 0402; Dev Tools Status: Production; Voltage: 50V; Temperature Coeffcient: 100ppm/C; Power: 1/10W; Owner: Tad Ahlvers; Populated: YES
U12 = IC1056: Gate AND; Manufacturer 1: Texas Instruments; MCHP-ID: IC1056; Description_: IC LOGIC SN74LVC1G08DBVR Single AND Gate SOT-23-5; Dev Tools Status: Production; Owner: Stephen Humberd; Populated: YES
U15 = MIC7448: Manufacturer 1: Microchip Technology; Description_: MCHP INTERFACE USB HUBx4 USB2534I-1080AEN SQFN-36; Dev Tools Status: Design; Owner: Dragos Danaila; Populated: YES
U16 U17 = IC1155: Manufacturer 1: Micrel Inc; MCHP-ID: IC1155; Description_: IC SWITCHER MIC2026-1YM Dual-Channel Power Distribution Switch SOIC-8; Dev Tools Status: Production; Vin: +2.7V to +5.5V; Owner: Jairuz Agang-ang; Populated: Yes
Y5 = MIC7861: Manufacturer 1: Microchip Technology; Description_: MCHP CLOCK OSCILLATOR 24MHz DSC1001CI5-024.0000 DFN-4; Dev Tools Status: Design; Owner: Ilie Galan; Populated: YES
